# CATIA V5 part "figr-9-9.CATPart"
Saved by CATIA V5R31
Part number: Part1
Bounding box of the stored display mesh (mm): x -15.705 to 88.369, y 0 to 286.83, z -20.723 to 20.723
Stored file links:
  D:\PROJECTS\Project 2021\US EDITION\CATIA V5 6R 2021\Resources\Part Files\c09_catia_v5_6r2021_prt\c09_catia_v5_6r2021_prt\figr-9-9.CATPart
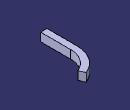
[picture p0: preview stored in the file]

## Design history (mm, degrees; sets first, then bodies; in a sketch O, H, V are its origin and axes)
Body1 (main body)
  Sketch1 on xy-plane, origin (0, 0, 0), H (1, 0, 0), V (0, 1, 0)
    line L1 (0, 0) -> (0, 150)
    arc A1 centre (131.8599, 150) radius 131.8599 from (0, 150) to (82.4884, 272.2681) cw
    length L1 = 150
    tangency: A1 L1
  Sketch2 on zx-plane, origin (0, 0, 0), H (-1, 0, 0), V (0, 0, 1)
    line L1 (15.7048, 20.7231) -> (15.7048, -20.7231)
    line L2 (15.7048, -20.7231) -> (-15.7048, -20.7231)
    line L3 (-15.7048, -20.7231) -> (-15.7048, 20.7231)
    line L4 (-15.7048, 20.7231) -> (15.7048, 20.7231)
    vertical: L1 V, L3 V
    horizontal: L2 H, L4 H
    equidistance: L1 L3 O, L2 L4 O
  Rib1: profile Sketch2, centre curve Sketch1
